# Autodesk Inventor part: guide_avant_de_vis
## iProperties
Shininess: 64.0
Length Units: 11269
Angle Units: 11279
Time Units: 11290
Mass Units: 11283
Length Display Precision: 3
Angle Display Precision: 2
Compacted: True
Part Number: guide_avant_de_vis
Document SubType Name: Modeling
Created: 2004-05
Material: Par défaut
Designer: David
Density: 0.0
Volumn: 0.0
Area: 0.0
PropertySet Name: Model Information
Control State: 0
Master: False
Checked Out: False
Author: David
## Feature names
1. Révolution1 [Revolution]
2. Extrusion1
